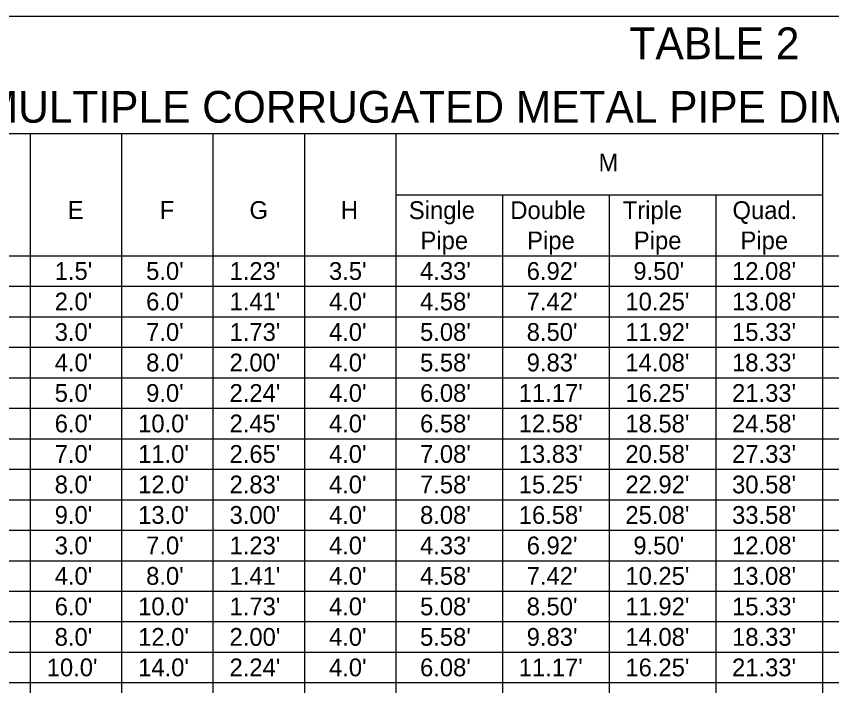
# Model space of a CAD drawing. Extents: x 1.7 to 14.4, y 0 to 7.8.
# Drawn here: x 4.886 to 8.096, y 5.118 to 7.752 of the extents above; entities that cross this region are included whole.
import ezdxf

# ---------------------------------------------------------------- set-up
doc = ezdxf.new("R2010")
doc.units = 0
doc.layers.add('Table', color=7, linetype='Continuous')

msp = doc.modelspace()

# ---------------------------------------------------------------- linework, layer by layer
at = {"layer": 'Table'}
msp.add_line((1.94, 7.7524), (13.46, 7.7524), dxfattribs=at)
for points in [[(13.46, 7.29), (11.78, 7.29), (10.1, 7.29), (8.42, 7.29), (8.06, 7.29), (6.38, 7.29), (6.02, 7.29), (5.66, 7.29), (5.3, 7.29), (4.94, 7.29), (4.52, 7.29), (4.04, 7.29), (3.62, 7.29), (3.2, 7.29), (2.9, 7.29), (2.6, 7.29), (2.3, 7.29), (1.94, 7.29)], [(4.94, 7.29), (4.94, 6.81), (4.94, 6.69), (4.94, 6.57), (4.94, 6.45), (4.94, 6.33), (4.94, 6.21), (4.94, 6.09), (4.94, 5.97), (4.94, 5.85), (4.94, 5.73), (4.94, 5.61), (4.94, 5.49), (4.94, 5.37), (4.94, 5.25), (4.94, 5.13), (4.94, 5.01)], [(5.3, 7.29), (5.3, 6.81), (5.3, 6.69), (5.3, 6.57), (5.3, 6.45), (5.3, 6.33), (5.3, 6.21), (5.3, 6.09), (5.3, 5.97), (5.3, 5.85), (5.3, 5.73), (5.3, 5.61), (5.3, 5.49), (5.3, 5.37), (5.3, 5.25), (5.3, 5.13), (5.3, 5.01)], [(5.66, 7.29), (5.66, 6.81), (5.66, 6.69), (5.66, 6.57), (5.66, 6.45), (5.66, 6.33), (5.66, 6.21), (5.66, 6.09), (5.66, 5.97), (5.66, 5.85), (5.66, 5.73), (5.66, 5.61), (5.66, 5.49), (5.66, 5.37), (5.66, 5.25), (5.66, 5.13), (5.66, 5.01)], [(6.02, 7.29), (6.02, 6.81), (6.02, 6.69), (6.02, 6.57), (6.02, 6.45), (6.02, 6.33), (6.02, 6.21), (6.02, 6.09), (6.02, 5.97), (6.02, 5.85), (6.02, 5.73), (6.02, 5.61), (6.02, 5.49), (6.02, 5.37), (6.02, 5.25), (6.02, 5.13), (6.02, 5.01)], [(6.38, 7.29), (6.38, 6.81), (6.38, 6.69), (6.38, 6.57), (6.38, 6.45), (6.38, 6.33), (6.38, 6.21), (6.38, 6.09), (6.38, 5.97), (6.38, 5.85), (6.38, 5.73), (6.38, 5.61), (6.38, 5.49), (6.38, 5.37), (6.38, 5.25), (6.38, 5.13), (6.38, 5.01)], [(8.06, 7.29), (8.06, 6.81), (8.06, 6.69), (8.06, 6.57), (8.06, 6.45), (8.06, 6.33), (8.06, 6.21), (8.06, 6.09), (8.06, 5.97), (8.06, 5.85), (8.06, 5.73), (8.06, 5.61), (8.06, 5.49), (8.06, 5.37), (8.06, 5.25), (8.06, 5.13), (8.06, 5.01)], [(6.38, 7.05), (6.8, 7.05), (7.22, 7.05), (7.64, 7.05), (8.06, 7.05)], [(6.8, 7.05), (6.8, 6.81), (6.8, 6.69), (6.8, 6.57), (6.8, 6.45), (6.8, 6.33), (6.8, 6.21), (6.8, 6.09), (6.8, 5.97), (6.8, 5.85), (6.8, 5.73), (6.8, 5.61), (6.8, 5.49), (6.8, 5.37), (6.8, 5.25), (6.8, 5.13), (6.8, 5.01)], [(7.22, 7.05), (7.22, 6.81), (7.22, 6.69), (7.22, 6.57), (7.22, 6.45), (7.22, 6.33), (7.22, 6.21), (7.22, 6.09), (7.22, 5.97), (7.22, 5.85), (7.22, 5.73), (7.22, 5.61), (7.22, 5.49), (7.22, 5.37), (7.22, 5.25), (7.22, 5.13), (7.22, 5.01)], [(7.64, 7.05), (7.64, 6.81), (7.64, 6.69), (7.64, 6.57), (7.64, 6.45), (7.64, 6.33), (7.64, 6.21), (7.64, 6.09), (7.64, 5.97), (7.64, 5.85), (7.64, 5.73), (7.64, 5.61), (7.64, 5.49), (7.64, 5.37), (7.64, 5.25), (7.64, 5.13), (7.64, 5.01)], [(1.7, 6.81), (1.94, 6.81), (2.3, 6.81), (2.6, 6.81), (2.9, 6.81), (3.2, 6.81), (3.62, 6.81), (4.04, 6.81), (4.52, 6.81), (4.94, 6.81), (5.3, 6.81), (5.66, 6.81), (6.02, 6.81), (6.38, 6.81), (6.8, 6.81), (7.22, 6.81), (7.64, 6.81), (8.06, 6.81), (8.42, 6.81)], [(2.3, 6.69), (2.6, 6.69), (2.9, 6.69), (3.2, 6.69), (3.62, 6.69), (4.04, 6.69), (4.52, 6.69), (4.94, 6.69), (5.3, 6.69), (5.66, 6.69), (6.02, 6.69), (6.38, 6.69), (6.8, 6.69), (7.22, 6.69), (7.64, 6.69), (8.06, 6.69), (8.42, 6.69)], [(2.3, 6.57), (2.6, 6.57), (2.9, 6.57), (3.2, 6.57), (3.62, 6.57), (4.04, 6.57), (4.52, 6.57), (4.94, 6.57), (5.3, 6.57), (5.66, 6.57), (6.02, 6.57), (6.38, 6.57), (6.8, 6.57), (7.22, 6.57), (7.64, 6.57), (8.06, 6.57), (8.42, 6.57)], [(2.3, 6.45), (2.6, 6.45), (2.9, 6.45), (3.2, 6.45), (3.62, 6.45), (4.04, 6.45), (4.52, 6.45), (4.94, 6.45), (5.3, 6.45), (5.66, 6.45), (6.02, 6.45), (6.38, 6.45), (6.8, 6.45), (7.22, 6.45), (7.64, 6.45), (8.06, 6.45), (8.42, 6.45)], [(2.3, 6.33), (2.6, 6.33), (2.9, 6.33), (3.2, 6.33), (3.62, 6.33), (4.04, 6.33), (4.52, 6.33), (4.94, 6.33), (5.3, 6.33), (5.66, 6.33), (6.02, 6.33), (6.38, 6.33), (6.8, 6.33), (7.22, 6.33), (7.64, 6.33), (8.06, 6.33), (8.42, 6.33)], [(2.3, 6.21), (2.6, 6.21), (2.9, 6.21), (3.2, 6.21), (3.62, 6.21), (4.04, 6.21), (4.52, 6.21), (4.94, 6.21), (5.3, 6.21), (5.66, 6.21), (6.02, 6.21), (6.38, 6.21), (6.8, 6.21), (7.22, 6.21), (7.64, 6.21), (8.06, 6.21), (8.42, 6.21)], [(2.3, 6.09), (2.6, 6.09), (2.9, 6.09), (3.2, 6.09), (3.62, 6.09), (4.04, 6.09), (4.52, 6.09), (4.94, 6.09), (5.3, 6.09), (5.66, 6.09), (6.02, 6.09), (6.38, 6.09), (6.8, 6.09), (7.22, 6.09), (7.64, 6.09), (8.06, 6.09), (8.42, 6.09)], [(2.3, 5.97), (2.6, 5.97), (2.9, 5.97), (3.2, 5.97), (3.62, 5.97), (4.04, 5.97), (4.52, 5.97), (4.94, 5.97), (5.3, 5.97), (5.66, 5.97), (6.02, 5.97), (6.38, 5.97), (6.8, 5.97), (7.22, 5.97), (7.64, 5.97), (8.06, 5.97), (8.42, 5.97)], [(2.3, 5.85), (2.6, 5.85), (2.9, 5.85), (3.2, 5.85), (3.62, 5.85), (4.04, 5.85), (4.52, 5.85), (4.94, 5.85), (5.3, 5.85), (5.66, 5.85), (6.02, 5.85), (6.38, 5.85), (6.8, 5.85), (7.22, 5.85), (7.64, 5.85), (8.06, 5.85), (8.42, 5.85)], [(1.94, 5.73), (2.3, 5.73), (2.6, 5.73), (2.9, 5.73), (3.2, 5.73), (3.62, 5.73), (4.04, 5.73), (4.52, 5.73), (4.94, 5.73), (5.3, 5.73), (5.66, 5.73), (6.02, 5.73), (6.38, 5.73), (6.8, 5.73), (7.22, 5.73), (7.64, 5.73), (8.06, 5.73), (8.42, 5.73)], [(2.3, 5.61), (2.6, 5.61), (2.9, 5.61), (3.2, 5.61), (3.62, 5.61), (4.04, 5.61), (4.52, 5.61), (4.94, 5.61), (5.3, 5.61), (5.66, 5.61), (6.02, 5.61), (6.38, 5.61), (6.8, 5.61), (7.22, 5.61), (7.64, 5.61), (8.06, 5.61), (8.42, 5.61)], [(2.3, 5.49), (2.6, 5.49), (2.9, 5.49), (3.2, 5.49), (3.62, 5.49), (4.04, 5.49), (4.52, 5.49), (4.94, 5.49), (5.3, 5.49), (5.66, 5.49), (6.02, 5.49), (6.38, 5.49), (6.8, 5.49), (7.22, 5.49), (7.64, 5.49), (8.06, 5.49), (8.42, 5.49)], [(2.3, 5.37), (2.6, 5.37), (2.9, 5.37), (3.2, 5.37), (3.62, 5.37), (4.04, 5.37), (4.52, 5.37), (4.94, 5.37), (5.3, 5.37), (5.66, 5.37), (6.02, 5.37), (6.38, 5.37), (6.8, 5.37), (7.22, 5.37), (7.64, 5.37), (8.06, 5.37), (8.42, 5.37)], [(2.3, 5.25), (2.6, 5.25), (2.9, 5.25), (3.2, 5.25), (3.62, 5.25), (4.04, 5.25), (4.52, 5.25), (4.94, 5.25), (5.3, 5.25), (5.66, 5.25), (6.02, 5.25), (6.38, 5.25), (6.8, 5.25), (7.22, 5.25), (7.64, 5.25), (8.06, 5.25), (8.42, 5.25)], [(2.3, 5.13), (2.6, 5.13), (2.9, 5.13), (3.2, 5.13), (3.62, 5.13), (4.04, 5.13), (4.52, 5.13), (4.94, 5.13), (5.3, 5.13), (5.66, 5.13), (6.02, 5.13), (6.38, 5.13), (6.8, 5.13), (7.22, 5.13), (7.64, 5.13), (8.06, 5.13), (8.42, 5.13)]]:
    msp.add_lwpolyline(points, dxfattribs=at)

# ---------------------------------------------------------------- texts
for s, height, p in [('TABLE 2', 0.125, (7.3001, 7.5837)), ('SINGLE AND MULTIPLE CORRUGATED METAL PIPE DIMENSIONS AND QUANTITIES', 0.125, (3.6948, 7.3337)), ('M', 0.07, (7.1783, 7.1419)), ('E', 0.07, (5.0882, 6.955)), ('F', 0.07, (5.4503, 6.955)), ('G', 0.07, (5.8038, 6.955)), ('H', 0.07, (6.1637, 6.955)), ('Single', 0.07, (6.4314, 6.9545)), ('Double', 0.07, (6.8309, 6.9545)), ('Triple', 0.07, (7.2737, 6.9545)), ('Quad.', 0.07, (7.7057, 6.9545)), ('Pipe', 0.07, (6.4773, 6.8355)), ('Pipe', 0.07, (6.8973, 6.8355)), ('Pipe', 0.07, (7.3173, 6.8355)), ('Pipe', 0.07, (7.7373, 6.8355))]:
    msp.add_text(s, height=height, dxfattribs=at).set_placement(p)
for s, p in [("1.5'", (5.0369, 6.715)), ("5.0'", (5.3969, 6.715)), ("1.23'", (5.7254, 6.715)), ("3.5'", (6.1169, 6.715)), ("4.33'", (6.4754, 6.715)), ("6.92'", (6.8954, 6.715)), ("9.50'", (7.3154, 6.715)), ("12.08'", (7.704, 6.715)), ("2.0'", (5.0369, 6.595)), ("6.0'", (5.3969, 6.595)), ("1.41'", (5.7254, 6.595)), ("4.0'", (6.1169, 6.595)), ("4.58'", (6.4754, 6.595)), ("7.42'", (6.8954, 6.595)), ("10.25'", (7.284, 6.595)), ("13.08'", (7.704, 6.595)), ("3.0'", (5.0369, 6.475)), ("7.0'", (5.3969, 6.475)), ("1.73'", (5.7254, 6.475)), ("4.0'", (6.1169, 6.475)), ("5.08'", (6.4754, 6.475)), ("8.50'", (6.8954, 6.475)), ("11.92'", (7.284, 6.475)), ("15.33'", (7.704, 6.475)), ("4.0'", (5.0369, 6.355)), ("8.0'", (5.3969, 6.355)), ("2.00'", (5.7254, 6.355)), ("4.0'", (6.1169, 6.355)), ("5.58'", (6.4754, 6.355)), ("9.83'", (6.8954, 6.355)), ("14.08'", (7.284, 6.355)), ("18.33'", (7.704, 6.355)), ("5.0'", (5.0369, 6.235)), ("9.0'", (5.3969, 6.235)), ("2.24'", (5.7254, 6.235)), ("4.0'", (6.1169, 6.235)), ("6.08'", (6.4754, 6.235)), ("11.17'", (6.864, 6.235)), ("16.25'", (7.284, 6.235)), ("21.33'", (7.704, 6.235)), ("6.0'", (5.0369, 6.115)), ("10.0'", (5.3654, 6.115)), ("2.45'", (5.7254, 6.115)), ("4.0'", (6.1169, 6.115)), ("6.58'", (6.4754, 6.115)), ("12.58'", (6.864, 6.115)), ("18.58'", (7.284, 6.115)), ("24.58'", (7.704, 6.115)), ("7.0'", (5.0369, 5.995)), ("11.0'", (5.3654, 5.995)), ("2.65'", (5.7254, 5.995)), ("4.0'", (6.1169, 5.995)), ("7.08'", (6.4754, 5.995)), ("13.83'", (6.864, 5.995)), ("20.58'", (7.284, 5.995)), ("27.33'", (7.704, 5.995)), ("8.0'", (5.0369, 5.875)), ("12.0'", (5.3654, 5.875)), ("2.83'", (5.7254, 5.875)), ("4.0'", (6.1169, 5.875)), ("7.58'", (6.4754, 5.875)), ("15.25'", (6.864, 5.875)), ("22.92'", (7.284, 5.875)), ("30.58'", (7.704, 5.875)), ("9.0'", (5.0369, 5.755)), ("13.0'", (5.3654, 5.755)), ("3.00'", (5.7254, 5.755)), ("4.0'", (6.1169, 5.755)), ("8.08'", (6.4754, 5.755)), ("16.58'", (6.864, 5.755)), ("25.08'", (7.284, 5.755)), ("33.58'", (7.704, 5.755)), ("3.0'", (5.0369, 5.635)), ("7.0'", (5.3969, 5.635)), ("1.23'", (5.7254, 5.635)), ("4.0'", (6.1169, 5.635)), ("4.33'", (6.4754, 5.635)), ("6.92'", (6.8954, 5.635)), ("9.50'", (7.3154, 5.635)), ("12.08'", (7.704, 5.635)), ("4.0'", (5.0369, 5.515)), ("8.0'", (5.3969, 5.515)), ("1.41'", (5.7254, 5.515)), ("4.0'", (6.1169, 5.515)), ("4.58'", (6.4754, 5.515)), ("7.42'", (6.8954, 5.515)), ("10.25'", (7.284, 5.515)), ("13.08'", (7.704, 5.515)), ("6.0'", (5.0369, 5.395)), ("10.0'", (5.3654, 5.395)), ("1.73'", (5.7254, 5.395)), ("4.0'", (6.1169, 5.395)), ("5.08'", (6.4754, 5.395)), ("8.50'", (6.8954, 5.395)), ("11.92'", (7.284, 5.395)), ("15.33'", (7.704, 5.395)), ("8.0'", (5.0369, 5.275)), ("12.0'", (5.3654, 5.275)), ("2.00'", (5.7254, 5.275)), ("4.0'", (6.1169, 5.275)), ("5.58'", (6.4754, 5.275)), ("9.83'", (6.8954, 5.275)), ("14.08'", (7.284, 5.275)), ("18.33'", (7.704, 5.275)), ("10.0'", (5.0054, 5.155)), ("14.0'", (5.3654, 5.155)), ("2.24'", (5.7254, 5.155)), ("4.0'", (6.1169, 5.155)), ("6.08'", (6.4754, 5.155)), ("11.17'", (6.864, 5.155)), ("16.25'", (7.284, 5.155)), ("21.33'", (7.704, 5.155))]:
    msp.add_text(s, height=0.07, rotation=0, dxfattribs=at).set_placement(p)

doc.saveas('drawing.dxf')
